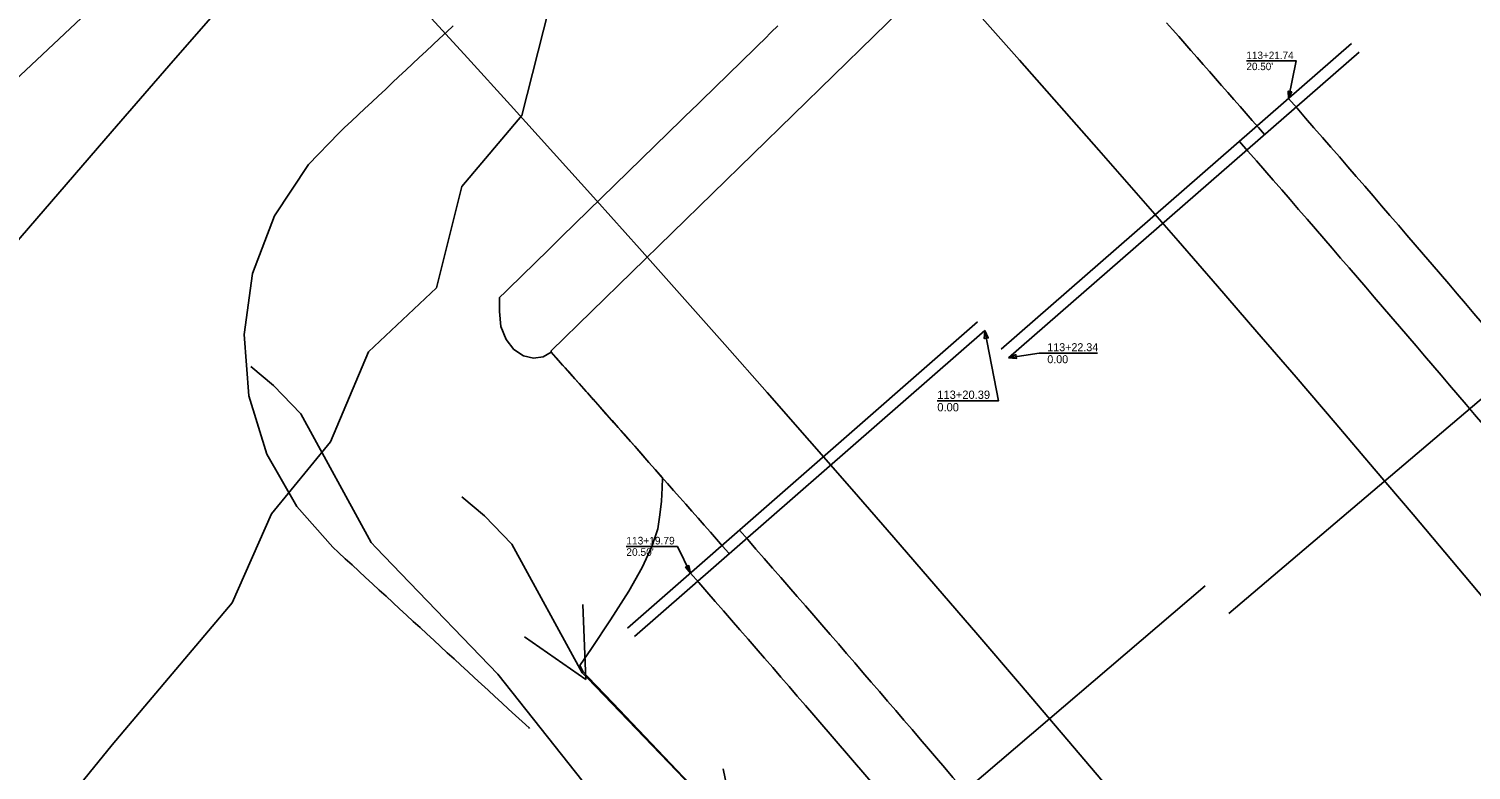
# Model space of a CAD drawing. Extents: x 1006695 to 1009377, y 1883329 to 1886115.
# Drawn here: x 1007928.2 to 1008005.8, y 1884600.5 to 1884640.3 of the extents above; entities that cross this region are included whole.
import ezdxf

# ---------------------------------------------------------------- set-up
doc = ezdxf.new("R2010")
doc.units = 0
for name, color, linetype in [('B_Bottom Cut', 7, 'Continuous'), ('B_Hatch', 7, 'Continuous'), ('B_Top Bench', 7, 'Continuous'), ('R_I-30 Information', 7, 'Continuous'), ('R_No Plot', 7, 'Continuous'), ('R_Prop Const Limits Cut', 7, 'Continuous'), ('R_Prop EOL', 7, 'Continuous'), ('R_Prop EOS', 7, 'Continuous'), ('R_Prop Guardrail', 7, 'Continuous')]:
    doc.layers.add(name, color=color, linetype=linetype)

msp = doc.modelspace()

# ---------------------------------------------------------------- linework, layer by layer
at = {"layer": 'B_Bottom Cut'}
msp.add_lwpolyline([(1007951.015, 1884640.499), (1007950.651, 1884640.156), (1007950.286, 1884639.814), (1007949.921, 1884639.472), (1007949.557, 1884639.13), (1007949.192, 1884638.787), (1007948.827, 1884638.445), (1007948.463, 1884638.103), (1007948.098, 1884637.761), (1007947.734, 1884637.418), (1007947.369, 1884637.076), (1007947.004, 1884636.734), (1007946.64, 1884636.392), (1007946.275, 1884636.05), (1007945.91, 1884635.707), (1007945.546, 1884635.365), (1007945.181, 1884635.023), (1007944.897, 1884634.756), (1007944.867, 1884634.728), (1007943.235, 1884633.036), (1007941.41, 1884630.278), (1007940.235, 1884627.175), (1007939.77, 1884623.892), (1007940.034, 1884620.601), (1007941.001, 1884617.473), (1007942.605, 1884614.662), (1007944.542, 1884612.466), (1007944.848, 1884612.182), (1007945.214, 1884611.845), (1007945.579, 1884611.509), (1007945.945, 1884611.172), (1007946.311, 1884610.836), (1007946.676, 1884610.499), (1007947.042, 1884610.162), (1007947.408, 1884609.826), (1007947.773, 1884609.489), (1007948.139, 1884609.152), (1007948.505, 1884608.816), (1007948.871, 1884608.479), (1007949.237, 1884608.142), (1007949.603, 1884607.805), (1007949.969, 1884607.469), (1007950.335, 1884607.132), (1007950.701, 1884606.795), (1007951.067, 1884606.458), (1007951.433, 1884606.121), (1007951.799, 1884605.784), (1007952.165, 1884605.447), (1007952.531, 1884605.11), (1007952.897, 1884604.773), (1007953.263, 1884604.436), (1007953.63, 1884604.099), (1007953.996, 1884603.762), (1007954.362, 1884603.425), (1007954.728, 1884603.088), (1007955.095, 1884602.751), (1007955.12, 1884602.728)], dxfattribs=at)
at = {"layer": 'B_Hatch'}
for p, q in [((1007956.291, 1884623.016), (1007982.37, 1884648.46)), ((1007956.291, 1884623.016), (1007982.37, 1884648.46)), ((1007962.135, 1884614.212), (1007962.211, 1884614.943)), ((1007962.135, 1884614.212), (1007962.211, 1884614.943)), ((1007962.027, 1884613.451), (1007962.135, 1884614.212)), ((1007962.027, 1884613.451), (1007962.135, 1884614.212)), ((1007961.696, 1884612.497), (1007962.027, 1884613.451)), ((1007961.696, 1884612.497), (1007962.027, 1884613.451)), ((1007961.178, 1884611.379), (1007961.696, 1884612.497)), ((1007961.178, 1884611.379), (1007961.696, 1884612.497)), ((1007960.467, 1884610.093), (1007961.178, 1884611.379)), ((1007960.467, 1884610.093), (1007961.178, 1884611.379)), ((1007959.48, 1884608.566), (1007960.467, 1884610.093)), ((1007959.48, 1884608.566), (1007960.467, 1884610.093)), ((1007958.462, 1884607.014), (1007959.48, 1884608.566)), ((1007958.462, 1884607.014), (1007959.48, 1884608.566)), ((1007957.819, 1884606.099), (1007958.462, 1884607.014)), ((1007957.819, 1884606.099), (1007958.462, 1884607.014))]:
    msp.add_line(p, q, dxfattribs=at)
for points in [[(1007931.903, 1884641.741), (1007927.138, 1884637.261)], [(1007962.211, 1884614.943), (1007962.256, 1884615.649), (1007962.271, 1884616.198)], [(1007962.211, 1884614.943), (1007962.256, 1884615.649), (1007962.271, 1884616.198)], [(1007962.271, 1884616.198), (1007962.271, 1884616.198)], [(1007962.271, 1884616.198), (1007962.271, 1884616.198)], [(1007958.271, 1884605.482), (1007958.007, 1884605.759), (1007957.819, 1884606.099)], [(1007958.271, 1884605.482), (1007958.007, 1884605.759), (1007957.819, 1884606.099)], [(1007965.034, 1884598.37), (1007964.774, 1884598.651), (1007959.593, 1884604.099), (1007958.271, 1884605.482)], [(1007965.034, 1884598.37), (1007964.774, 1884598.651), (1007959.593, 1884604.099), (1007958.271, 1884605.482)]]:
    msp.add_lwpolyline(points, dxfattribs=at)
for centre, radius, start, end in [((1007956.326, 1884622.98), 0.05, 134.29379, 205.15642), ((1007956.326, 1884622.98), 0.05, 134.29379, 205.15642), ((1007956.326, 1884622.98), 0.05, 205.15642, 221.73941), ((1007956.326, 1884622.98), 0.05, 205.15642, 221.73941), ((1006901.082, 1883681.489), 1414.144, 41.374013, 41.739411), ((1006901.082, 1883681.489), 1414.144, 41.374013, 41.739411)]:
    msp.add_arc(centre, radius, start, end, dxfattribs=at)
at = {"layer": 'B_Top Bench'}
for points in [[(1007968.481, 1884640.497), (1007968.123, 1884640.148), (1007967.765, 1884639.799), (1007967.407, 1884639.449), (1007967.049, 1884639.1), (1007966.691, 1884638.751), (1007966.333, 1884638.402), (1007965.975, 1884638.053), (1007965.618, 1884637.704), (1007965.26, 1884637.354), (1007964.902, 1884637.005), (1007964.544, 1884636.656), (1007964.186, 1884636.307), (1007963.828, 1884635.958), (1007963.47, 1884635.609), (1007963.112, 1884635.259), (1007962.755, 1884634.91), (1007962.397, 1884634.561), (1007962.039, 1884634.212), (1007961.681, 1884633.863), (1007961.323, 1884633.514), (1007960.965, 1884633.164), (1007960.607, 1884632.815), (1007960.249, 1884632.466), (1007959.891, 1884632.117), (1007959.534, 1884631.768), (1007959.176, 1884631.419), (1007958.818, 1884631.069), (1007958.46, 1884630.72), (1007958.102, 1884630.371), (1007957.744, 1884630.022), (1007957.386, 1884629.673), (1007957.028, 1884629.324), (1007956.67, 1884628.974), (1007956.313, 1884628.625), (1007955.955, 1884628.276), (1007955.597, 1884627.927), (1007955.239, 1884627.578), (1007954.881, 1884627.229), (1007954.523, 1884626.879), (1007954.165, 1884626.53), (1007953.807, 1884626.181), (1007953.528, 1884625.909), (1007953.5, 1884625.881), (1007953.511, 1884625.143), (1007953.586, 1884624.32), (1007953.858, 1884623.623), (1007954.279, 1884623.093), (1007954.792, 1884622.756), (1007955.338, 1884622.625), (1007955.856, 1884622.695), (1007956.289, 1884622.946), (1007956.569, 1884622.633), (1007956.901, 1884622.259), (1007957.234, 1884621.886), (1007957.566, 1884621.512), (1007957.899, 1884621.139), (1007958.231, 1884620.765), (1007958.563, 1884620.391), (1007958.895, 1884620.017), (1007959.227, 1884619.643), (1007959.558, 1884619.269), (1007959.89, 1884618.895), (1007960.221, 1884618.52), (1007960.552, 1884618.146), (1007960.883, 1884617.771), (1007961.214, 1884617.396), (1007961.545, 1884617.022), (1007961.876, 1884616.647), (1007962.206, 1884616.271), (1007962.537, 1884615.896), (1007962.867, 1884615.521), (1007963.197, 1884615.145), (1007963.527, 1884614.77), (1007963.857, 1884614.394), (1007964.187, 1884614.018), (1007964.517, 1884613.642), (1007964.846, 1884613.266), (1007965.176, 1884612.89), (1007965.505, 1884612.514), (1007965.834, 1884612.137), (1007965.857, 1884612.112)], [(1007994.638, 1884634.644), (1007994.309, 1884635.021), (1007993.98, 1884635.397), (1007993.652, 1884635.774), (1007993.323, 1884636.151), (1007992.993, 1884636.527), (1007992.664, 1884636.903), (1007992.335, 1884637.279), (1007992.005, 1884637.655), (1007991.676, 1884638.031), (1007991.346, 1884638.407), (1007991.016, 1884638.783), (1007990.686, 1884639.159), (1007990.356, 1884639.534), (1007990.026, 1884639.91), (1007989.695, 1884640.285), (1007989.365, 1884640.66)]]:
    msp.add_lwpolyline(points, dxfattribs=at)
at = {"layer": 'R_I-30 Information'}
for points in [[(1007979.454, 1884680.26), (1007976.507, 1884676.202), (1007973.904, 1884671.845), (1007971.943, 1884666.933), (1007969.954, 1884662.046), (1007967.909, 1884657.207), (1007965.202, 1884652.939), (1007962.682, 1884648.97), (1007958.28, 1884646.15), (1007956.165, 1884641.385), (1007954.708, 1884635.667), (1007951.479, 1884631.848), (1007950.127, 1884626.416), (1007946.456, 1884622.973), (1007944.424, 1884618.126), (1007941.255, 1884614.256), (1007939.136, 1884609.483), (1007935.908, 1884605.665), (1007932.68, 1884601.847), (1007929.207, 1884597.562), (1007926.27, 1884593.488)], [(1007926.14, 1884627.261), (1007929.413, 1884631.04), (1007932.687, 1884634.82), (1007935.962, 1884638.601), (1007939.236, 1884642.38), (1007942.51, 1884646.16), (1007945.918, 1884650.096), (1007949.192, 1884653.876), (1007952.466, 1884657.655), (1007955.574, 1884661.242), (1007958.848, 1884665.022), (1007962.122, 1884668.801), (1007965.395, 1884672.58), (1007968.669, 1884676.36), (1007971.943, 1884680.139)]]:
    msp.add_lwpolyline(points, dxfattribs=at)
at = {"layer": 'R_No Plot'}
for p, q in [((1007999.325, 1884639.539), (1007980.486, 1884623.105)), ((1007999.726, 1884639.079), (1007980.88, 1884622.652)), ((1007993.669, 1884638.607), (1007995.949, 1884638.607)), ((1007960.386, 1884608.113), (1007979.203, 1884624.573)), ((1008011.771, 1884625.081), (1007992.719, 1884608.895)), ((1007960.774, 1884607.67), (1007979.598, 1884624.122)), ((1007982.963, 1884622.893), (1007985.667, 1884622.893)), ((1007977.048, 1884620.326), (1007979.89, 1884620.326)), ((1007960.327, 1884612.51), (1007962.668, 1884612.51)), ((1007972.425, 1884594.168), (1007991.455, 1884610.38)), ((1007958.146, 1884605.358), (1007957.99, 1884609.38)), ((1007958.146, 1884605.358), (1007954.852, 1884607.65)), ((1007966.36, 1884596.623), (1007965.527, 1884600.559))]:
    msp.add_line(p, q, dxfattribs=at)
for points in [[(1007995.934, 1884636.581), (1007996.348, 1884638.607), (1007995.949, 1884638.607)], [(1007979.598, 1884624.122), (1007980.336, 1884620.326), (1007979.89, 1884620.326)], [(1007980.88, 1884622.652), (1007982.533, 1884622.893), (1007982.963, 1884622.893)], [(1007940.141, 1884622.178), (1007941.356, 1884621.157), (1007942.821, 1884619.636), (1007946.605, 1884612.712), (1007946.87, 1884612.436), (1007948.197, 1884611.056), (1007953.413, 1884605.639), (1007959.509, 1884597.953), (1007965.602, 1884590.27), (1007971.693, 1884582.589), (1007973.002, 1884580.938), (1007977.63, 1884574.786), (1007983.508, 1884566.943), (1007989.415, 1884559.128), (1007995.325, 1884551.319), (1008001.212, 1884543.496), (1008007.077, 1884535.656), (1008010.286, 1884531.346), (1008012.918, 1884527.801), (1008018.737, 1884519.93), (1008022.875, 1884514.285), (1008024.627, 1884512.11), (1008031.122, 1884504.719), (1008037.596, 1884497.297)], [(1007951.489, 1884615.178), (1007952.704, 1884614.157), (1007954.169, 1884612.636), (1007957.953, 1884605.712), (1007958.218, 1884605.436), (1007958.232, 1884605.421), (1007959.545, 1884604.056), (1007964.761, 1884598.639)], [(1007963.773, 1884611.076), (1007963.078, 1884612.51), (1007962.668, 1884612.51)]]:
    msp.add_lwpolyline(points, dxfattribs=at)
for points in [[(1007995.934, 1884636.581), (1007995.917, 1884636.979), (1007996.106, 1884636.941)], [(1007979.598, 1884624.122), (1007979.787, 1884623.717), (1007979.574, 1884623.676)], [(1007980.88, 1884622.652), (1007981.278, 1884622.816), (1007981.308, 1884622.609)], [(1007963.773, 1884611.076), (1007963.511, 1884611.39), (1007963.689, 1884611.477)]]:
    msp.add_lwpolyline(points, close=True, dxfattribs=at)
at = {"layer": 'R_Prop Const Limits Cut'}
msp.add_lwpolyline([(1007927.138, 1884637.261), (1007931.903, 1884641.741)], dxfattribs=at)
at = {"layer": 'R_Prop EOL'}
for radius, start in [(1443.394, 37.045062), (1421.394, 35.651642)]:
    msp.add_arc((1006901.082, 1883681.489), radius, start, 53.471968, dxfattribs=at)
at = {"layer": 'R_Prop EOS'}
for radius, start, end in [(1452.894, 39.349748, 41.099748), (1411.894, 39.427748, 41.177748)]:
    msp.add_arc((1006901.082, 1883681.489), radius, start, end, dxfattribs=at)
at = {"layer": 'R_Prop Guardrail'}
for radius, start, end in [(1449.394, 39.349748, 41.099748), (1415.394, 39.427748, 41.177748)]:
    msp.add_arc((1006901.082, 1883681.489), radius, start, end, dxfattribs=at)

# ---------------------------------------------------------------- texts
at = {"layer": 'R_No Plot'}
for s, height, p in [("20.50'", 0.3989, (1007993.669, 1884638.109)), ('113+21.74', 0.3989, (1007993.669, 1884638.707)), ('113+22.34', 0.4304, (1007982.963, 1884623)), ('0.00', 0.4304, (1007982.963, 1884622.355)), ('113+20.39', 0.4462, (1007977.048, 1884620.438)), ('0.00', 0.4462, (1007977.048, 1884619.768)), ('113+19.79', 0.4091, (1007960.327, 1884612.613)), ("20.50'", 0.4091, (1007960.327, 1884611.999))]:
    msp.add_text(s, height=height, dxfattribs=at).set_placement(p)

doc.saveas('drawing.dxf')
